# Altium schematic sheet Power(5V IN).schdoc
size 420 x 297 mm; Symbol: Drawing-Symbol_A4; Company: 嘉立创EDA; Version: V1.0; Page Size: A4; @Project Name: A113 Android MircroPhone; @Page Count: 5; @Update Date: 2025-12-04; @Create Date: 2025-08-01; @Schematic Name: Schematic1; @Page No: 1; @Page Name: Power(12V IN); @Create Time: 21:43:32; @Update Time: 13:55:02; Border: 1; Width: 1655; Height: 1170; Region Start: 1; X Region Count: 6; Y Region Count: 4; Blade Width: 10; Title Block Position: 3; @Board Name: Board1; Device: Drawing-Symbol_A4
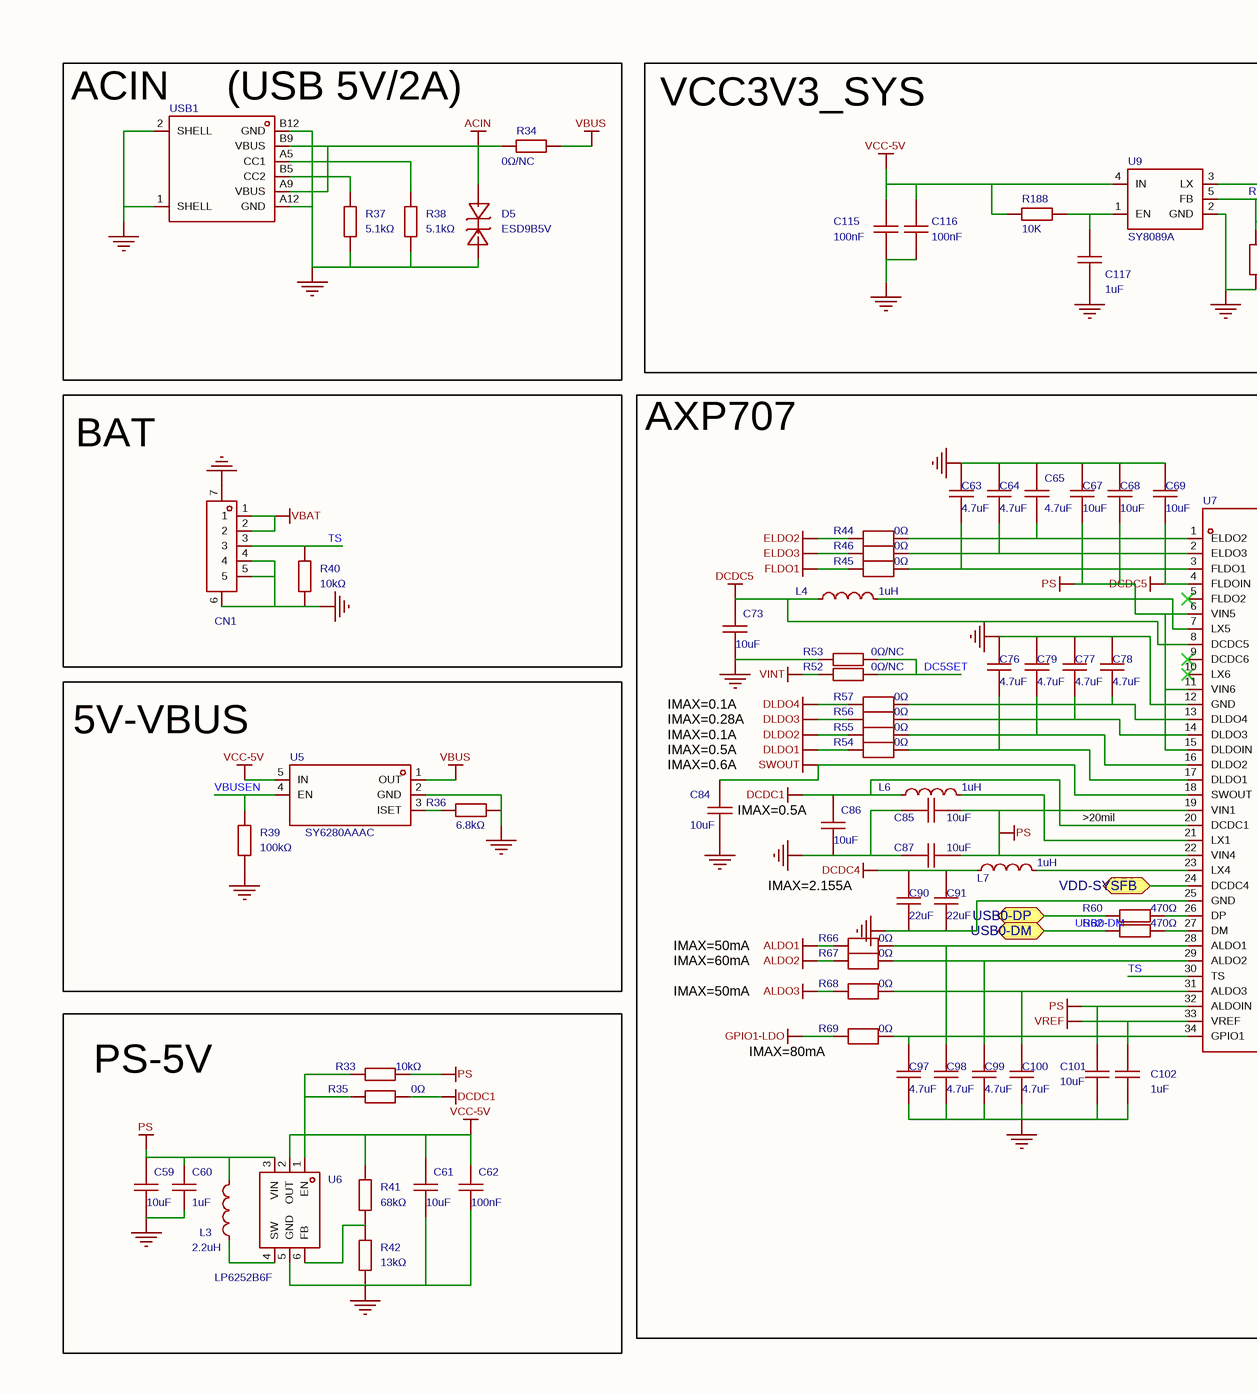
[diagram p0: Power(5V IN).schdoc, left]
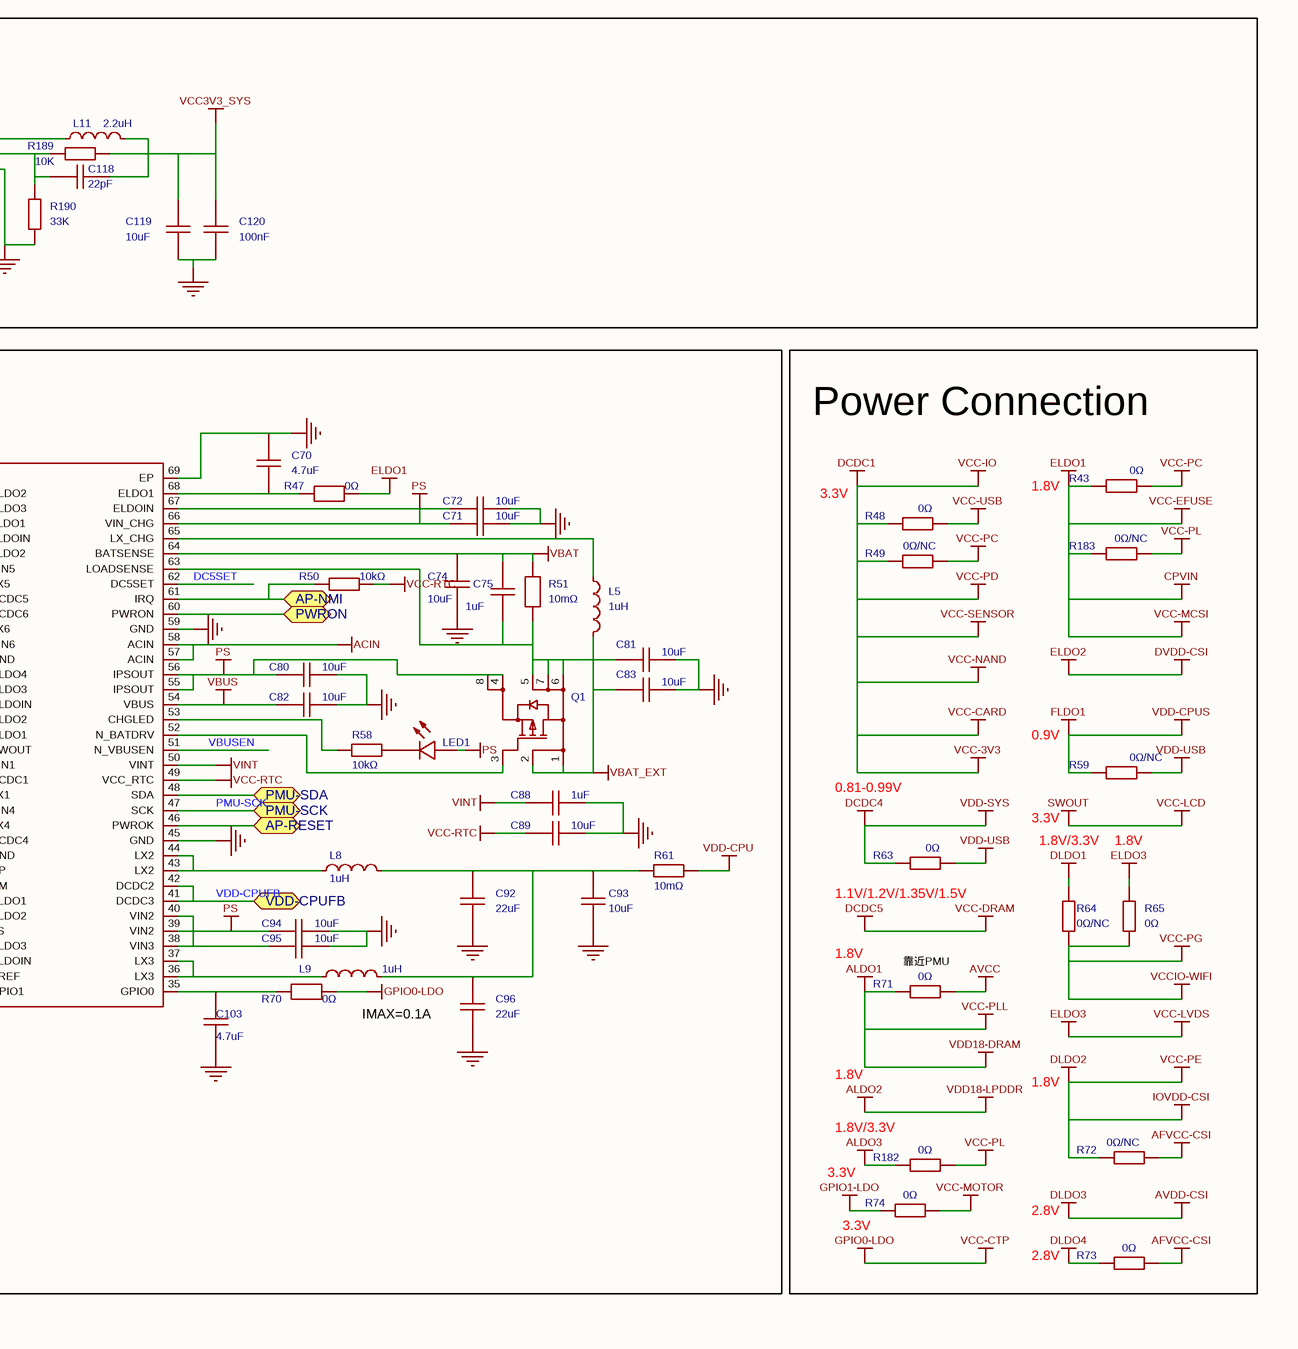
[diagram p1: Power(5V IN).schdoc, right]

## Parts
C59  10uF  [C0603]
C60  1uF  [C0402]
C61  10uF  [C0603]
C62  100nF  [C0402]
C63  4.7uF  [C0402]
C64  4.7uF  [C0402]
C65  4.7uF  [C0402]
C67  10uF  [C0603]
C68  10uF  [C0603]
C69  10uF  [C0603]
C70  4.7uF  [C0402]
C71  10uF  [C0603]
C72  10uF  [C0603]
C73  10uF  [C0603]
C74  10uF  [C0603]
C75  1uF  [C0402]
C76  4.7uF  [C0402]
C77  4.7uF  [C0402]
C78  4.7uF  [C0402]
C79  4.7uF  [C0402]
C80  10uF  [C0603]
C81  10uF  [C0603]
C82  10uF  [C0603]
C83  10uF  [C0603]
C84  10uF  [C0603]
C85  10uF  [C0603]
C86  10uF  [C0603]
C87  10uF  [C0603]
C88  1uF  [C0402]
C89  10uF  [C0603]
C90  22uF  [C0603]
C91  22uF  [C0603]
C92  22uF  [C0603]
C93  10uF  [C0603]
C94  10uF  [C0603]
C95  10uF  [C0603]
C96  22uF  [C0603]
C97  4.7uF  [C0402]
C98  4.7uF  [C0402]
C99  4.7uF  [C0402]
C100  4.7uF  [C0402]
C101  10uF  [C0603]
C102  1uF  [C0402]
C103  4.7uF  [C0402]
C115  100nF  [C0603]
C116  100nF  [C0603]
C117  1uF  [C0603]
C118  22pF  [C0603]
C119  10uF  [C0603]
C120  100nF  [C0603]
CN1  1.25K-CB-5PWB  [CONN-SMD_5P-P1.25_L5.5-W11.4-5PWB]  (value not drawn)
D5  ESD9B5V  [SOD-923_L0.8-W0.6-LS1.0-BI-1]
L3  2.2uH  [IND-SMD_L3.0-W3.0]
L4  1uH  [IND-SMD_L2.5-W2.0_MHCH252012A]
L5  1uH  [IND-SMD_L2.5-W2.0_MHCH252012A]
L6  1uH  [IND-SMD_L2.5-W2.0_MHCH252012A]
L7  1uH  [IND-SMD_L2.5-W2.0_MHCH252012A]
L8  1uH  [IND-SMD_L2.5-W2.0_MHCH252012A]
L9  1uH  [IND-SMD_L2.5-W2.0_MHCH252012A]
L11  2.2uH  [IND-SMD_L3.0-W3.0]
LED1  XL-1606UGC  [LED-SMD_L1.7-W1.1-R-RD_GREEN]  (value not drawn)
Q1  CJM1216  [DFN-6L_L2.0-W2.0-P0.65-BL_CJM1216]  (value not drawn)
R33  10kΩ  [R0402]
R34  0Ω/NC  [R0805]
R35  0Ω  [R0402]
R36  6.8kΩ  [R0402]
R37  5.1kΩ  [R0402]
R38  5.1kΩ  [R0402]
R39  100kΩ  [R0402]
R40  10kΩ  [R0402]
R41  68kΩ  [R0402]
R42  13kΩ  [R0402]
R43  0Ω  [R0402]
R44  0Ω  [R0402]
R45  0Ω  [R0402]
R46  0Ω  [R0402]
R47  0Ω  [R0402]
R48  0Ω  [R0402]
R49  0Ω/NC  [R0402]
R50  10kΩ  [R0402]
R51  10mΩ  [R0805]
R52  0Ω/NC  [R0402]
R53  0Ω/NC  [R0402]
R54  0Ω  [R0402]
R55  0Ω  [R0402]
R56  0Ω  [R0402]
R57  0Ω  [R0402]
R58  10kΩ  [R0402]
R59  0Ω/NC  [R0402]
R60  470Ω  [R0402]
R61  10mΩ  [R0603]
R62  470Ω  [R0402]
R63  0Ω  [R0402]
R64  0Ω/NC  [R0402]
R65  0Ω  [R0402]
R66  0Ω  [R0402]
R67  0Ω  [R0402]
R68  0Ω  [R0402]
R69  0Ω  [R0402]
R70  0Ω  [R0402]
R71  0Ω  [R0402]
R72  0Ω/NC  [R0402]
R73  0Ω  [R0402]
R74  0Ω  [R0402]
R182  0Ω  [R0402]
R183  0Ω/NC  [R0402]
R188  10K  [R0603]
R189  10K  [R0603]
R190  33K  [R0603]
U5  SY6280AAAC  [TSOT-23-5_L2.9-W1.6-P0.95-LS2.8-BL]
U6  LP6252B6F  [SOT-23-6_L2.9-W1.6-P0.95-LS2.8-BL]
U7  AXP707  [QFN-68_L8.0-W8.0-P0.40-BL-EP5.5]  (value not drawn)
U9  SY8089A  [SOT-23-5_L3.0-W1.7-P0.95-LS2.8-BL]
USB1  TYPE-C 6P(040新)  [USB-C-SMD_TYPE-C-6P]  (value not drawn)

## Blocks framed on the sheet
ACIN     (USB 5V/2A): D5 R34 R37 R38 USB1
VCC3V3_SYS: C115-C120 L11 R188-R190 U9
BAT: CN1 R40
AXP707: C63-C65 C67-C103 L4-L9 LED1 Q1 R44-R47 R50-R58 R60-R62 R66-R70 U7
Power Connection: R43 R48 R49 R59 R63-R65 R71-R74 R182 R183
5V-VBUS: R36 R39 U5
PS-5V: C59-C62 L3 R33 R35 R41 R42 U6

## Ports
AP-NMI (bidir), AP-RESET (bidir), PMU-SCK (bidir), PMU-SDA (bidir), PWRON (bidir), USB0-DM (bidir), USB0-DP (bidir), VDD-CPUFB (bidir), VDD-SYSFB (bidir)

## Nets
ACIN: D5.2(A) R34.1 U7.57(ACIN) U7.58(ACIN) USB1.A9(VBUS) USB1.B9(VBUS)
AFVCC-CSI: R72.2 R73.2
ALDO1: R66.1 R71.1  [also labelled VCC-PLL, VDD18-DRAM]
ALDO2: R67.1  [also labelled VDD18-LPDDR]
ALDO3: R68.1 R182.1
AVCC: R71.2
AVDD-CSI: R56.2  [also labelled DLDO3]
CPVIN: R43.1 R47.1 R183.1  [also labelled ELDO1, VCC-EFUSE, VCC-MCSI]
DCDC1: C86.2 L6.1 R35.2 R48.1 R49.1 U7.20(DCDC1)  [also labelled VCC-3V3, VCC-CARD, VCC-IO, VCC-NAND, VCC-PD, VCC-SENSOR]
DCDC4: C90.2 C91.2 L7.1 R63.1  [also labelled VDD-SYS]
DCDC5: C69.2 C73.2 L4.1 U7.4(FLDOIN) U7.8(DCDC5)  [also labelled VCC-DRAM]
DLDO1: R54.2 R64.2
DLDO2: R55.2 R72.1  [also labelled IOVDD-CSI, VCC-PE]
DLDO4: R57.2 R73.1
DVDD-CSI: R44.2  [also labelled ELDO2]
ELDO3: R46.2 R65.2  [also labelled VCC-LVDS]
FLDO1: R45.2 R59.1  [also labelled VDD-CPUS]
GND: C59.1 C60.2 C61.1 C62.1 C63.1 C64.1 C65.1 C67.1 C68.1 C69.1 C70.1 C71.2 C72.2 C73.1 C74.2 C76.1 C77.1 C78.1 C79.1 C80.2 C81.2 C82.2 C83.2 C84.2 C85.1 C86.1 C87.1 C88.1 C89.1 C90.1 C91.1 C92.1 C93.2 C94.2 C95.2 C96.1 C97.1 C98.1 C99.1 C100.1 C101.2 C102.2 C103.1 C115.1 C116.1 C117.1 C119.1 C120.1 CN1.4 CN1.5 CN1.6 CN1.7 D5.1(C) R36.1 R37.1 R38.1 R39.1 R40.1 R42.1 R53.1 R190.1 U5.2(GND) U6.5(GND) U7.12(GND) U7.25(GND) U7.45(GND) U7.59(GND) U7.69(EP) U9.2(GND) USB1.1(SHELL) USB1.2(SHELL) USB1.A12(GND) USB1.B12(GND)
GPIO0-LDO: R70.2  [also labelled VCC-CTP]
GPIO1-LDO: R69.2 R74.1
PS: C59.2 C60.1 C67.2 C68.2 C71.1 C72.1 C80.1 C85.2 C87.2 C94.1 C95.1 C101.1 L3.2 LED1.2(A) Q1.4(S) Q1.8(S) R33.2 U6.3(VIN) U7.6(VIN5) U7.11(VIN6) U7.15(DLDOIN) U7.19(VIN1) U7.22(VIN4) U7.32(ALDOIN) U7.38(VIN3) U7.39(VIN2) U7.40(VIN2) U7.55(IPSOUT) U7.56(IPSOUT) U7.66(VIN_CHG) U7.67(ELDOIN)
SWOUT: C84.1 U7.18(SWOUT)  [also labelled VCC-LCD]
VBAT: C74.1 C75.2 CN1.1 CN1.2 R51.2 U7.64(BATSENSE)
VBAT_EXT: C75.1 C81.1 C83.1 L5.2 Q1.1(D) Q1.2(D) Q1.5(D) Q1.6(D) Q1.7(D) R51.1 U7.63(LOADSENSE)
VBUS: C82.1 R34.2 U5.1(OUT) U7.54(VBUS)
VCC3V3_SYS: C118.2 C119.2 C120.2 L11.2 R189.2
VCC-5V: C61.2 C62.2 C115.2 C116.2 R41.2 R188.1 U5.5(IN) U6.2(OUT) U9.4(IN)
VCC-MOTOR: R74.2
VCC-PC: R43.2 R49.2
VCC-PG: R64.1 R65.1  [also labelled VCCIO-WIFI]
VCC-PL: R182.2 R183.2
VCC-RTC: C89.2 R50.2 U7.49(VCC_RTC)
VCC-USB: R48.2
VDD-CPU: R61.2
VDD-USB: R59.2 R63.2
VINT: C88.2 R52.1 U7.50(VINT)
VREF: C102.1 U7.33(VREF)
AP-NMI: R50.1 U7.61(IRQ) ; port AP-NMI
AP-RESET: U7.46(PWROK) ; port AP-RESET
DC5SET: R52.2 R53.2 U7.62(DC5SET)
PMU-SCK: U7.47(SCK) ; port PMU-SCK
PMU-SDA: U7.48(SDA) ; port PMU-SDA
PWRON: U7.60(PWRON) ; port PWRON
TS: CN1.3 R40.2 U7.30(TS)
USB0-DM: R62.1 ; port USB0-DM
USB0-DP: R60.1 ; port USB0-DP
VBUSEN: R39.2 U5.4(EN) U7.51(N_VBUSEN)
VDD-CPUFB: U7.41(DCDC3) U7.42(DCDC2) ; port VDD-CPUFB
VDD-SYSFB: U7.24(DCDC4) ; port VDD-SYSFB
NetC63_2: C63.2 R45.1 U7.3(FLDO1)
NetC64_2: C64.2 R46.1 U7.2(ELDO3)
NetC65_2: C65.2 R44.1 U7.1(ELDO2)
NetC70_2: C70.2 R47.2 U7.68(ELDO1)
NetC76_2: C76.2 R54.1 U7.17(DLDO1)
NetC77_2: C77.2 R56.1 U7.14(DLDO3)
NetC78_2: C78.2 R57.1 U7.13(DLDO4)
NetC79_2: C79.2 R55.1 U7.16(DLDO2)
NetC92_2: C92.2 C93.1 C96.2 L8.2 L9.2 R61.1
NetC97_2: C97.2 R69.1 U7.34(GPIO1)
NetC98_2: C98.2 R66.2 U7.28(ALDO1)
NetC99_2: C99.2 R67.2 U7.29(ALDO2)
NetC100_2: C100.2 R68.2 U7.31(ALDO3)
NetC103_2: C103.2 R70.1 U7.35(GPIO0)
NetC117_2: C117.2 R188.2 U9.1(EN)
NetC118_1: C118.1 R189.1 R190.2 U9.5(FB)
NetL3_1: L3.1 U6.4(SW)
NetL4_2: L4.2 U7.7(LX5)
NetL5_1: L5.1 U7.65(LX_CHG)
NetL6_2: L6.2 U7.21(LX1)
NetL7_2: L7.2 U7.23(LX4)
NetL8_1: L8.1 U7.43(LX2) U7.44(LX2)
NetL9_1: L9.1 U7.36(LX3) U7.37(LX3)
NetL11_1: L11.1 U9.3(LX)
NetLED1_1: LED1.1(K) R58.2
NetQ1_3: Q1.3(G) U7.52(N_BATDRV)
NetR33_1: R33.1 R35.1 U6.1(EN)
NetR36_2: R36.2 U5.3(ISET)
NetR37_2: R37.2 USB1.B5(CC2)
NetR38_2: R38.2 USB1.A5(CC1)
NetR41_1: R41.1 R42.2 U6.6(FB)
NetR58_1: R58.1 U7.53(CHGLED)
NetR60_2: R60.2 U7.26(DP)
NetR62_2: R62.2 U7.27(DM)

Not connected (* = marked no-connect by the designer): U7 5(FLDO2)* 9(DCDC6)* 10(LX6)*

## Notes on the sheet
- 3.3V
- (near R43) 1.8V
- IMAX=0.1A
- IMAX=0.28A
- (near C84) IMAX=0.5A
- (near C84) IMAX=0.6A
- (near R59) 0.9V
- IMAX=0.5A
- >20mil
- 0.81-0.99V
- IMAX=2.155A
- 1.8V/3.3V
- 1.8V
- IMAX=50mA
- IMAX=60mA
- (near R71) 1.8V
- (near R63) 1.1V/1.2V/1.35V/1.5V
- (near R69) IMAX=80mA
- (near R71) 靠近PMU
- (near R182) 1.8V/3.3V
- (near R74) 3.3V
- 2.8V
- (near R73) 2.8V

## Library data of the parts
C59 C61 C67-C69 C71-C74 C80-C87 C89 C93-C95 C101 = CL10A106KP8NNNC: 容值:10uF;精度:±10%;额定电压:10V;材质(温度系数):X5R;; Manufacturer: SAMSUNG(三星); AddInBom: yes; ModelId: ac125912035d415993ca9572d50418b1; ModelName: C0603_L1.6-W0.8-H0.8; ModelTransform: 62.992,31.496,0,0,0,0,0,0,0; Tolerance: ±10%; Voltage Rated: 10V; Temperature Coefficient: X5R
C60 C75 C88 C102 = CL05A105KP5NNNC: 容值:1uF;精度:±10%;额定电压:10V;材质(温度系数):X5R;; Manufacturer: SAMSUNG(三星); Symbol: CL05A105KA5NQNC; AddInBom: yes; ModelId: 36a51122f27c49738f86b3bfa98863e0; ModelName: C0402_L1.0-W0.5-H0.5; ModelTransform: 39.37,19.685,0,0,0,0,0,0,0; Tolerance: ±10%; Voltage Rated: 10V; Temperature Coefficient: X5R
C62 = CL05B104KO5NNNC: 容值:100nF;精度:±10%;额定电压:16V;材质(温度系数):X7R;; Manufacturer: SAMSUNG(三星); AddInBom: yes; ModelId: 36a51122f27c49738f86b3bfa98863e0; ModelName: C0402_L1.0-W0.5-H0.5; ModelTransform: 39.37,19.685,0,0,0,0,0,0,0; Tolerance: ±10%; Voltage Rated: 16V; Temperature Coefficient: X7R
C63-C65 C70 C76-C79 C97-C100 C103 = CL05A475MQ5NRNC: 容值:4.7uF;精度:±20%;额定电压:6.3V;材质(温度系数):X5R;; Manufacturer: SAMSUNG(三星); Symbol: CL05A475MQ5NRNC_C307423; AddInBom: yes; ModelId: 36a51122f27c49738f86b3bfa98863e0; ModelName: C0402_L1.0-W0.5-H0.5; ModelTransform: 39.37,19.685,0,0,0,0,0,0,0; Tolerance: ±20%; Voltage Rated: 6.3V; Temperature Coefficient: X5R
C90-C92 C96 = CL10A226MQ8NRNC: 容值:22uF;精度:±20%;额定电压:6.3V;材质(温度系数):X5R;; Manufacturer: SAMSUNG(三星); AddInBom: yes; ModelId: ac125912035d415993ca9572d50418b1; ModelName: C0603_L1.6-W0.8-H0.8; ModelTransform: 62.992,31.496,0,0,0,0,0,0,0; Tolerance: ±20%; Voltage Rated: 6.3V; Temperature Coefficient: X5R
C115-C120 = CAP_0603: ConvertToPcb: yes; SymbolName: CapAcitance; ModelId: ac125912035d415993ca9572d50418b1; ModelName: C0603_L1.6-W0.8-H0.8; ModelTransform: 62.992,31.496,0,0,0,0,0,0,0
CN1 = 1.25K-CB-5PWB: 参考系列:-;间距:1.25mm;插针结构:1x5P;排数:1;每排PIN数:5;行距:-;公母:公型插针;安装方式:卧贴;额定电流:1A;工作温度范围:-25℃~+85℃;; Manufacturer: HDGC(华德共创); AddInBom: yes; ModelId: 042ad1db120d4601993e305387badb9b; ModelTransform: 446.85,255.905,0,0,0,0,0,-5.909,0; Pitch: 1.25mm; Pins Structure: 1x5P; Number of PINs Per Row: 5; Gender: 公型插针; Current Rating (Max): 1A
D5 = ESD9B5V: Manufacturer: TECH PUBLIC(台舟); AddInBom: yes; ModelId: 2f595e76c437472fa7f031dc65d7fe13; ModelTransform: 39.37,23.622,0,0,0,0,-0.005,0,0
L3 = SWPA3015S2R2MT: 电感值:2.2uH;精度:±20%;额定电流:2A;; Manufacturer: Sunlord(顺络); AddInBom: yes; ModelId: 67451da4701445baa335959290a67a23; ModelName: IND-SMD_L3.0-W3.0-H1.5; ModelTransform: 118.11,118.8974,0,90,0,0,0,0,0; Tolerance: ±20%; Rated Current: 2A
L4-L9 = HEI252010A-1R0M-Q8: 电感值:1uH;精度:±20%;额定电流:3A;饱和电流(Isat):3.7A;; Manufacturer: chilisin(奇力新); AddInBom: yes; ModelId: 031f16169bf244cc8d318e03edbc44a5; ModelName: IND-SMD_L2.5-W2.0-H1.2_MHCH252012A; ModelTransform: 99.2124,79.527,0,0,0,0,0,0,0; Tolerance: ±20%; Rated Current: 3A; Saturation Current (Isat): 3.7A; DC Resistance (DCR): 45mΩ
L11 = SWPA3015S2R2NT: 电感值:2.2uH;精度:±30%;额定电流:1.6A;饱和电流(Isat):2A;类型:-;; Manufacturer: Sunlord(顺络); AddInBom: yes; ModelId: 67451da4701445baa335959290a67a23; ModelName: IND-SMD_L3.0-W3.0-H1.5; ModelTransform: 118.11,118.11394,0,0,0,0,0,0,0; Tolerance: ±30%; Current Rating: 1.6A; Current - Saturation(Isat): 2A; DC Resistance(DCR): 78mΩ
LED1 = XL-1606UGC: 发光颜色:翠绿;主波长:520nm~530nm;色温:-;功率:80mW;安装方式:侧贴;; Manufacturer: XINGLIGHT(成兴光); Symbol: FC-DA1608HRK-620D; AddInBom: yes; ModelId: 2d6731949e6b4efab495b902955be808; ModelTransform: 67.7164,43.7007,0,0,0,0,0,8.346,0; Emitted Color: 翠绿; Lens Color: 无色透明; Peak Wavelength: 535nm; Forward Current: 25mA; Power Dissipation: 80mW; Viewing Angle: 120°; Mounting Sytle: 侧贴
Q1 = CJM1216: 类型:P沟道;漏源电压(Vdss):12V;连续漏极电流(Id):16A;功率(Pd):2.5W;导通电阻(RDS(on)@Vgs,Id):21mΩ@4.5V,6.7A;阈值电压(Vgs(th)@Id):1V@250uA;; Manufacturer: CJ(江苏长电/长晶); AddInBom: yes; ModelId: 0b3e0b58484e47a2a6bad3a789cc7d0f; ModelName: DFN-6L_L2.0-W2.0-H0.8-P0.65-BL_CJM1216; ModelTransform: 79.527,79.527,0,0,0,0,-2.283,0,0; Type: P沟道; Drain Source Voltage (Vdss): 12V; Continuous Drain Current (Id): 16A; Power Dissipation (Pd): 2.5W
R33 R40 R50 R58 = RC0402FR-0710KL: 电阻类型:厚膜电阻;阻值:10kΩ;精度:±1%;功率:62.5mW;; Manufacturer: YAGEO(国巨); AddInBom: yes; ModelId: 671aefced39d4c318694bba8bd8efd39; ModelName: R0402_L1.0-W0.5-H0.5; ModelTransform: 39.37,19.685,0,0,0,0,0,0.0005,0; Tolerance: ±1%; Power(Watts): 62.5mW; Temperature Coefficient: ±100ppm/℃; Overload Voltage (Max): 50V
R34 = RC0805FR-070RL: 电阻类型:厚膜电阻;阻值:0Ω;精度:-;功率:125mW;; Manufacturer: YAGEO(国巨); AddInBom: yes; ModelId: 37a81e68749a4138bd2dfa6897b24b85; ModelName: R0805_L2.0-W1.3-H0.6; ModelTransform: 78.74,51.181,0,0,0,0,0,-0.0005,0; Power(Watts): 125mW; Overload Voltage (Max): 150V
R35 R43 R48 R63 R65 R71 R73 R183 = RC0402JR-070RL: 电阻类型:厚膜电阻;阻值:0Ω;精度:-;功率:62.5mW;; Manufacturer: YAGEO(国巨); AddInBom: yes; ModelId: 671aefced39d4c318694bba8bd8efd39; ModelName: R0402_L1.0-W0.5-H0.5; ModelTransform: 39.37,19.685,0,0,0,0,0,0.0005,0; Power(Watts): 62.5mW; Overload Voltage (Max): 50V
R36 = 0402WGF6801TCE: 电阻类型:厚膜电阻;阻值:6.8kΩ;精度:±1%;功率:62.5mW;; Manufacturer: UNI-ROYAL(厚声); AddInBom: yes; ModelId: 671aefced39d4c318694bba8bd8efd39; ModelName: R0402_L1.0-W0.5-H0.5; ModelTransform: 39.37,19.685,0,0,0,0,0,0.0005,0; Tolerance: ±1%; Power(Watts): 62.5mW; Temperature Coefficient: ±100ppm/℃; Overload Voltage (Max): 50V
R37 R38 = RC0402FR-075K1L: 电阻类型:厚膜电阻;阻值:5.1kΩ;精度:±1%;功率:62.5mW;; Manufacturer: YAGEO(国巨); AddInBom: yes; ModelId: 671aefced39d4c318694bba8bd8efd39; ModelName: R0402_L1.0-W0.5-H0.5; ModelTransform: 39.37,19.685,0,0,0,0,0,0.0005,0; Tolerance: ±1%; Power(Watts): 62.5mW; Temperature Coefficient: ±100ppm/℃; Overload Voltage (Max): 50V
R39 = 0402WGF1003TCE: 电阻类型:厚膜电阻;阻值:100kΩ;精度:±1%;功率:62.5mW;; Manufacturer: UNI-ROYAL(厚声); AddInBom: yes; ModelId: 671aefced39d4c318694bba8bd8efd39; ModelName: R0402_L1.0-W0.5-H0.5; ModelTransform: 39.37,19.685,0,0,0,0,0,0.0005,0; Tolerance: ±1%; Power(Watts): 62.5mW; Temperature Coefficient: ±100ppm/℃; Overload Voltage (Max): 50V
R41 = RC0402FR-0768KL: 电阻类型:厚膜电阻;阻值:68kΩ;精度:±1%;功率:62.5mW;; Manufacturer: YAGEO(国巨); AddInBom: yes; ModelId: 671aefced39d4c318694bba8bd8efd39; ModelName: R0402_L1.0-W0.5-H0.5; ModelTransform: 39.37,19.685,0,0,0,0,0,0.0005,0; Tolerance: ±1%; Power(Watts): 62.5mW; Temperature Coefficient: ±100ppm/℃; Overload Voltage (Max): 50V
R42 = RC0402FR-0713KL: 电阻类型:厚膜电阻;阻值:13kΩ;精度:±1%;功率:62.5mW;; Manufacturer: YAGEO(国巨); AddInBom: yes; ModelId: 671aefced39d4c318694bba8bd8efd39; ModelName: R0402_L1.0-W0.5-H0.5; ModelTransform: 39.37,19.685,0,0,0,0,0,0.0005,0; Tolerance: ±1%; Power(Watts): 62.5mW; Temperature Coefficient: ±100ppm/℃; Overload Voltage (Max): 50V
R44-R47 R54-R57 R66-R68 = RC0402FR-070RL: 电阻类型:厚膜电阻;阻值:0Ω;精度:-;功率:62.5mW;; Manufacturer: YAGEO(国巨); Symbol: RL0603FR-070R01L; AddInBom: yes; ModelId: 671aefced39d4c318694bba8bd8efd39; ModelName: R0402_L1.0-W0.5-H0.5; ModelTransform: 39.37,19.685,0,0,0,0,0,0.0005,0; Power(Watts): 62.5mW; Overload Voltage (Max): 50V
R49 R52 R53 R59 R64 R72 = RC0402JR-070RL: 电阻类型:厚膜电阻;阻值:0Ω;精度:-;功率:62.5mW;; Manufacturer: YAGEO(国巨); Standardization Check: false; AddInBom: yes; ModelId: 671aefced39d4c318694bba8bd8efd39; ModelName: R0402_L1.0-W0.5-H0.5; ModelTransform: 39.37,19.685,0,0,0,0,0,0.0005,0; Power(Watts): 62.5mW; Overload Voltage (Max): 50V
R51 = PA0805FRE470R01L: 阻值:10mΩ;精度:±1%;功率:500mW;; Manufacturer: YAGEO(国巨); AddInBom: yes; ModelId: 37a81e68749a4138bd2dfa6897b24b85; ModelName: R0805_L2.0-W1.3-H0.6; ModelTransform: 78.74,51.181,0,0,0,0,0,-0.0005,0; Tolerance: ±1%; Power(Watts): 500mW; Temperature Coefficient: ±50ppm/℃
R60 R62 = RC0402FR-07470RL: 电阻类型:厚膜电阻;阻值:470Ω;精度:±1%;功率:62.5mW;; Manufacturer: YAGEO(国巨); AddInBom: yes; ModelId: 671aefced39d4c318694bba8bd8efd39; ModelName: R0402_L1.0-W0.5-H0.5; ModelTransform: 39.37,19.685,0,0,0,0,0,0.0005,0; Tolerance: ±1%; Power(Watts): 62.5mW; Temperature Coefficient: ±100ppm/℃; Overload Voltage (Max): 50V
R61 = RL0603FR-070R01L: 电阻类型:-;阻值:10mΩ;精度:±1%;功率:100mW;安装方式:-;; Manufacturer: YAGEO(国巨); Symbol: RC0402FR-070RL; AddInBom: yes; ModelId: fc143cca1e79419f9cd78b61e9279f08; ModelTransform: 31.8897,63.7794,0,90,0,0,0,0,0; Tolerance: ±1%; Power(Watts): 100mW
R69 R70 = RC0402JR-070RL: 电阻类型:厚膜电阻;阻值:0Ω;精度:-;功率:62.5mW;; Manufacturer: YAGEO(国巨); Symbol: RL0603FR-070R01L; AddInBom: yes; ModelId: 671aefced39d4c318694bba8bd8efd39; ModelName: R0402_L1.0-W0.5-H0.5; ModelTransform: 39.37,19.685,0,0,0,0,0,0.0005,0; Power(Watts): 62.5mW; Overload Voltage (Max): 50V
R74 = 0402WGF0000TCE: 电阻类型:厚膜电阻;阻值:0Ω;精度:±1%;功率:62.5mW;; Manufacturer: UNI-ROYAL(厚声); Symbol: RC0402JR-070RL; AddInBom: yes; ModelId: 671aefced39d4c318694bba8bd8efd39; ModelName: R0402_L1.0-W0.5-H0.5; ModelTransform: 39.37,19.685,0,0,0,0,0,0.0005,0; Tolerance: ±1%; Power(Watts): 62.5mW; Temperature Coefficient: ±800ppm/℃; Overload Voltage (Max): 50V
R182 = 0402WGF0000TCE: 电阻类型:厚膜电阻;阻值:0Ω;精度:±1%;功率:62.5mW;; Manufacturer: UNI-ROYAL(厚声); Symbol: RC0402JR-070RL; Standardization Check: false; AddInBom: yes; ModelId: 671aefced39d4c318694bba8bd8efd39; ModelName: R0402_L1.0-W0.5-H0.5; ModelTransform: 39.37,19.685,0,0,0,0,0,0.0005,0; Tolerance: ±1%; Power(Watts): 62.5mW; Temperature Coefficient: ±800ppm/℃; Overload Voltage (Max): 50V
R188-R190 = Res_0603: ConvertToPcb: yes; SymbolName: 电阻; ModelId: fc143cca1e79419f9cd78b61e9279f08; ModelTransform: 31.8897,63.7794,0,90,0,0,0,0,0
U5 = SY6280AAAC: Manufacturer: silergy(矽力杰); AddInBom: yes; ModelId: b5108020abe84f7bb0f3c398b43b6e0b; ModelName: TSOT-23-5_L2.9-W1.6-H1.00-LS2.8-P0.95; ModelTransform: 110.45568,114.173,0,90,0,0,0.0005,0,0
U6 = LP6252B6F: 2.7A MOS电流  同步升压IC; Manufacturer: LOWPOWER(微源半导体); AddInBom: yes; ModelId: 18da8f6c14a34920b3e136b5c401a119; ModelName: SOT-23-6_L2.9-W1.6-H1.5-LS2.8-P0.95; ModelTransform: 110.236,113.364,0,90,0,0,0.0005,0.0005,0
U7 = AXP707: A PMU designed by Allwinner. PMIC Optimized For Multi-Core high-Performance SystemPMIC Optimi. Adapt A133; Manufacturer: x-powers; AddInBom: yes; ModelId: 2b113d81f9a64bbea21a80c3e4547c28; ModelName: QFN-68_L8.0-W8.0-H0.9-P0.40-BL-EP4.4; ModelTransform: 314.96,314.96,0,90,0,0,0.002,-0.001,0
U9 = SY8089A: 功能类型:降压型;输出类型:-;工作电压:2.5V~5.5V;输出电压:-;输出电流:-;; Manufacturer: TECH PUBLIC(台舟); AddInBom: yes; ModelId: 0a2a1b8f50944f73965918ad6e5fe167; ModelName: SOT-23-5_L2.9-W1.6-H1.1-LS2.8-P0.95; ModelTransform: 118.60433,114.173,0,90,0,0,0.0005,0.0005,0; Function: 降压型; Frequency - Switching: 1MHz; Synchronous Rectifier: 是; Number of Outputs: 1; Topology: 降压式; Switch tube (built-in/external): 内置
USB1 = TYPE-C 6P(040新): TYPE-C母座6PIN4脚插件壳长6.8mm铜壳外壳带丝印; Manufacturer: SHOU HAN(首韩); AddInBom: yes; ModelId: fb1418f8b16e47cdb24a4fea470b26a0; ModelTransform: 351.9678,267.716,0,0,0,0,0,-43.189,-39.37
